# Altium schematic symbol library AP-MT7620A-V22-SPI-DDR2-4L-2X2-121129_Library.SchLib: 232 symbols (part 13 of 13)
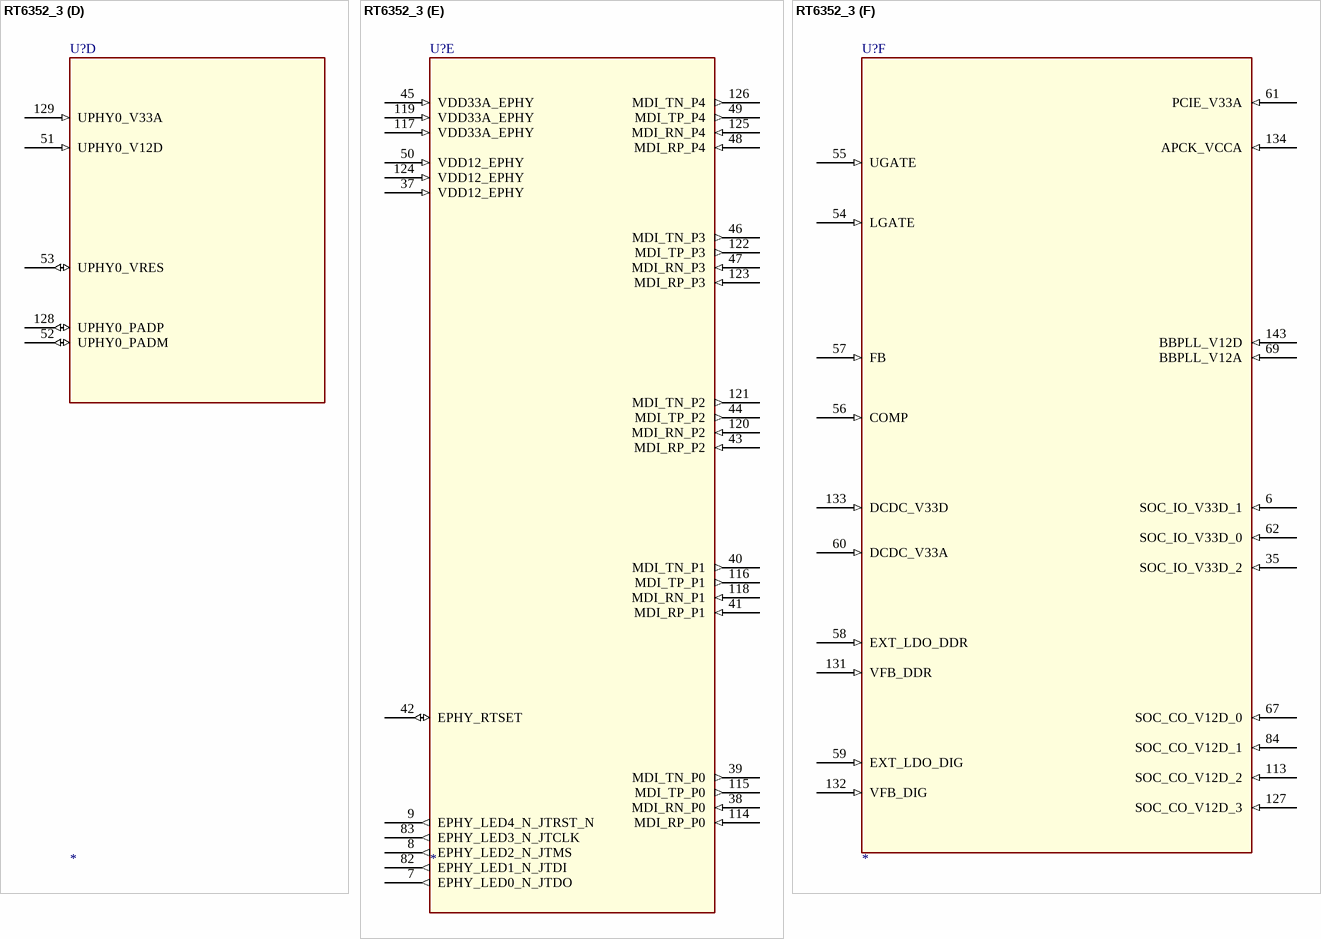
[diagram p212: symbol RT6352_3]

## RT6352_3
designator U?
footprint DRQFN148
part A pins: 1 RF0_PA2_V33N (in), 3 RF1_VX_LDO (out), 4 RF1_OUTP (out), 5 RF1_PA2_V33N (in), 66 PA_PE_G0 (out), 68 ANT_TRN (out), 71 RF_XI (out), 73 PLL_VC_CAP (out), 74 BG_EXTR (out), 75 RF0_OUTN (out), 76 RF0_PA1_V33A (in), 78 RF1_PA2_V33P (in), 79 RF1_OUTN (out), 80 RF1_PA1_V33A (in), 81 WLAN_LED_N (out), 140 PA_PE_G1 (out), 142 ANT_TRNB (out), 144 RF_XO (out), 145 RF_V12_XTAL (out), 146 PLL_VX_LDO (out), 147 BG_V33A (out), 148 RF0_VX_LDO (out), NC RF0_OUTP (out), NC RF0_PA2_V33P (in)
part B pins: 10 VDD18/VDD25 (in), 11 DDR_DQ9/DDR_DQ14 (io), 12 DDR_DQ11/DDR_DQ12 (io), 13 DDR_DQ13/DDR_DQ10 (io), 14 DDR_DQ15/DDR_DQ8 (io), 15 DDR_DQM1/DDR_DQM1 (io), 16 DDR_CLK_M (io), 17 DDR_ODT/DDR_MA4 (io), 18 DDR_IOC_V12D (in), 19 DDR_CAS_N/DDR_MA7 (io), 20 DDR_MA0/DDR_MA8 (io), 21 DDR_MA4/DDR_MA11 (io), 22 DDR_MA8/DDR_CKE (io), 23 DDR_DQ5/DDR_DQ0 (io), 24 DDR_DQ0/DDR_DQ2 (io), 25 DDR_DQ7/DDR_DQ3 (io), 27 DDR_DQ3/DDR_DQ7 (io), 28 DDR_DQM02/DDR_DQM0 (io), 29 DDR_MA12/DDR_MA2 (io), 30 VDD18/VDD25 (in), 31 DDR_MA3/DDR_MA10 (io), 31 DDR_DQM1/DDR_BA0 (io), 33 DDR_BA1/DDR_RAS_N (io), 34 DDR_CKE/DDR_WE_N (io), 85 DDR_DQ14/DDR_DQ15 (io), 86 DDR_DQ12/DDR_DQ13 (io), 87 DDR_DQ10/DDR_DQ11 (io), 88 DDR_DQ8/DDR_DQ9 (io), 89 DDR_DQS1/DDR_DQS1 (in), 90 DDR_VREF (in), 91 DDR_CLK_P (io), 93 DDR_RAS_N/DDR_MA5 (io), 93 VDD18/VDD25 (in), 94 DDR_CS_N/DDR2_MA6 (io), 95 VDD18/VDD25 (in), 96 DDR_MA2/DDR_MA9 (io), 97 DDR_MA6/DDR_MA12 (io), 98 DDR_MA11/DDR_ODT (io), 99 DDR_DQ2/DDR_DQ1 (io), 100 DDR_IOC_V12D (in), 101 DDR_DQ6/DDR_DQ4 (io), 102 DDR_DQ4/DDR_DQ6 (io), 103 DDR_DQS0/DDR_DQS0 (io), 104 DDR_MA9/DDR_MA3 (io), 105 DDR_MA7/DDR_MA1 (io), 106 DDR_MA5/DDR_MA0 (io), 107 DDR_DQ1/DDR_DQ5 (io), 107 DDR_MA1/DDR_BA1 (io), 108 DDR_BA0/DDR_CS_N (io), 109 DDR_WE_N/DDR_CAS_N (io), 110 DDR_VREF (in)
part C pins: 36 I2C_SD (out), 63 SPI_MOSI (out), 64 SPI_CS0 (out), 65 GPIO0 (io), 111 I2C_SCLK (io), 112 RXD2 (in), 130 PORST_N (in), 136 SPI_CLK (out), 137 SPI_MISO (in), 138 SPI_CS1 (out), 139 WDT_RST_N (in), NC TXD2 (out)
part D pins: 51 UPHY0_V12D (in), 52 UPHY0_PADM (io), 53 UPHY0_VRES (io), 128 UPHY0_PADP (io), 129 UPHY0_V33A (in)
part E pins: 7 EPHY_LED0_N_JTDO (out), 8 EPHY_LED2_N_JTMS (out), 9 EPHY_LED4_N_JTRST_N (out), 37 VDD12_EPHY (in), 38 MDI_RN_P0 (in), 39 MDI_TN_P0 (out), 40 MDI_TN_P1 (out), 41 MDI_RP_P1 (in), 42 EPHY_RTSET (io), 43 MDI_RP_P2 (in), 44 MDI_TP_P2 (out), 45 VDD33A_EPHY (in), 46 MDI_TN_P3 (out), 47 MDI_RN_P3 (in), 48 MDI_RP_P4 (in), 49 MDI_TP_P4 (out), 50 VDD12_EPHY (in), 82 EPHY_LED1_N_JTDI (out), 83 EPHY_LED3_N_JTCLK (out), 114 MDI_RP_P0 (in), 115 MDI_TP_P0 (out), 116 MDI_TP_P1 (out), 117 VDD33A_EPHY (in), 118 MDI_RN_P1 (in), 119 VDD33A_EPHY (in), 120 MDI_RN_P2 (in), 121 MDI_TN_P2 (out), 122 MDI_TP_P3 (out), 123 MDI_RP_P3 (in), 124 VDD12_EPHY (in), 125 MDI_RN_P4 (in), 126 MDI_TN_P4 (out)
part F pins: 6 SOC_IO_V33D_1 (in), 35 SOC_IO_V33D_2 (in), 54 LGATE (in), 55 UGATE (in), 56 COMP (in), 57 FB (in), 58 EXT_LDO_DDR (in), 59 EXT_LDO_DIG (in), 60 DCDC_V33A (in), 61 PCIE_V33A (in), 62 SOC_IO_V33D_0 (in), 67 SOC_CO_V12D_0 (in), 69 BBPLL_V12A (in), 84 SOC_CO_V12D_1 (in), 113 SOC_CO_V12D_2 (in), 127 SOC_CO_V12D_3 (in), 131 VFB_DDR (in), 132 VFB_DIG (in), 133 DCDC_V33D (in), 134 APCK_VCCA (in), 143 BBPLL_V12D (in)

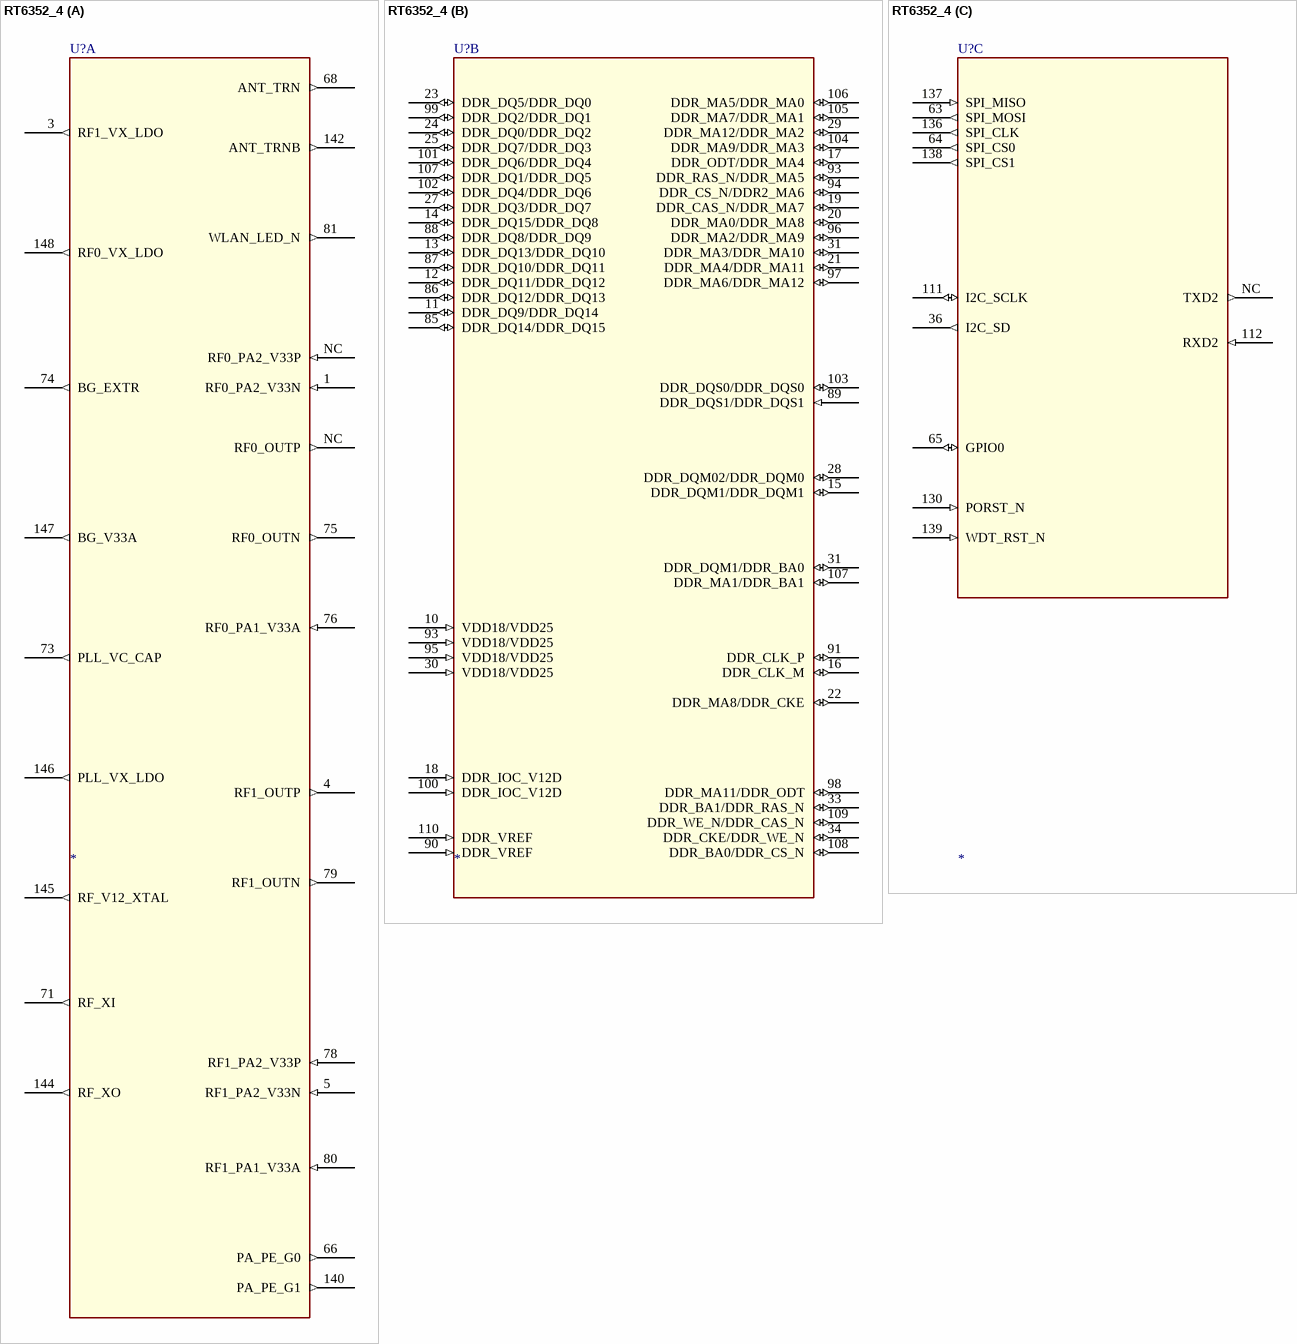
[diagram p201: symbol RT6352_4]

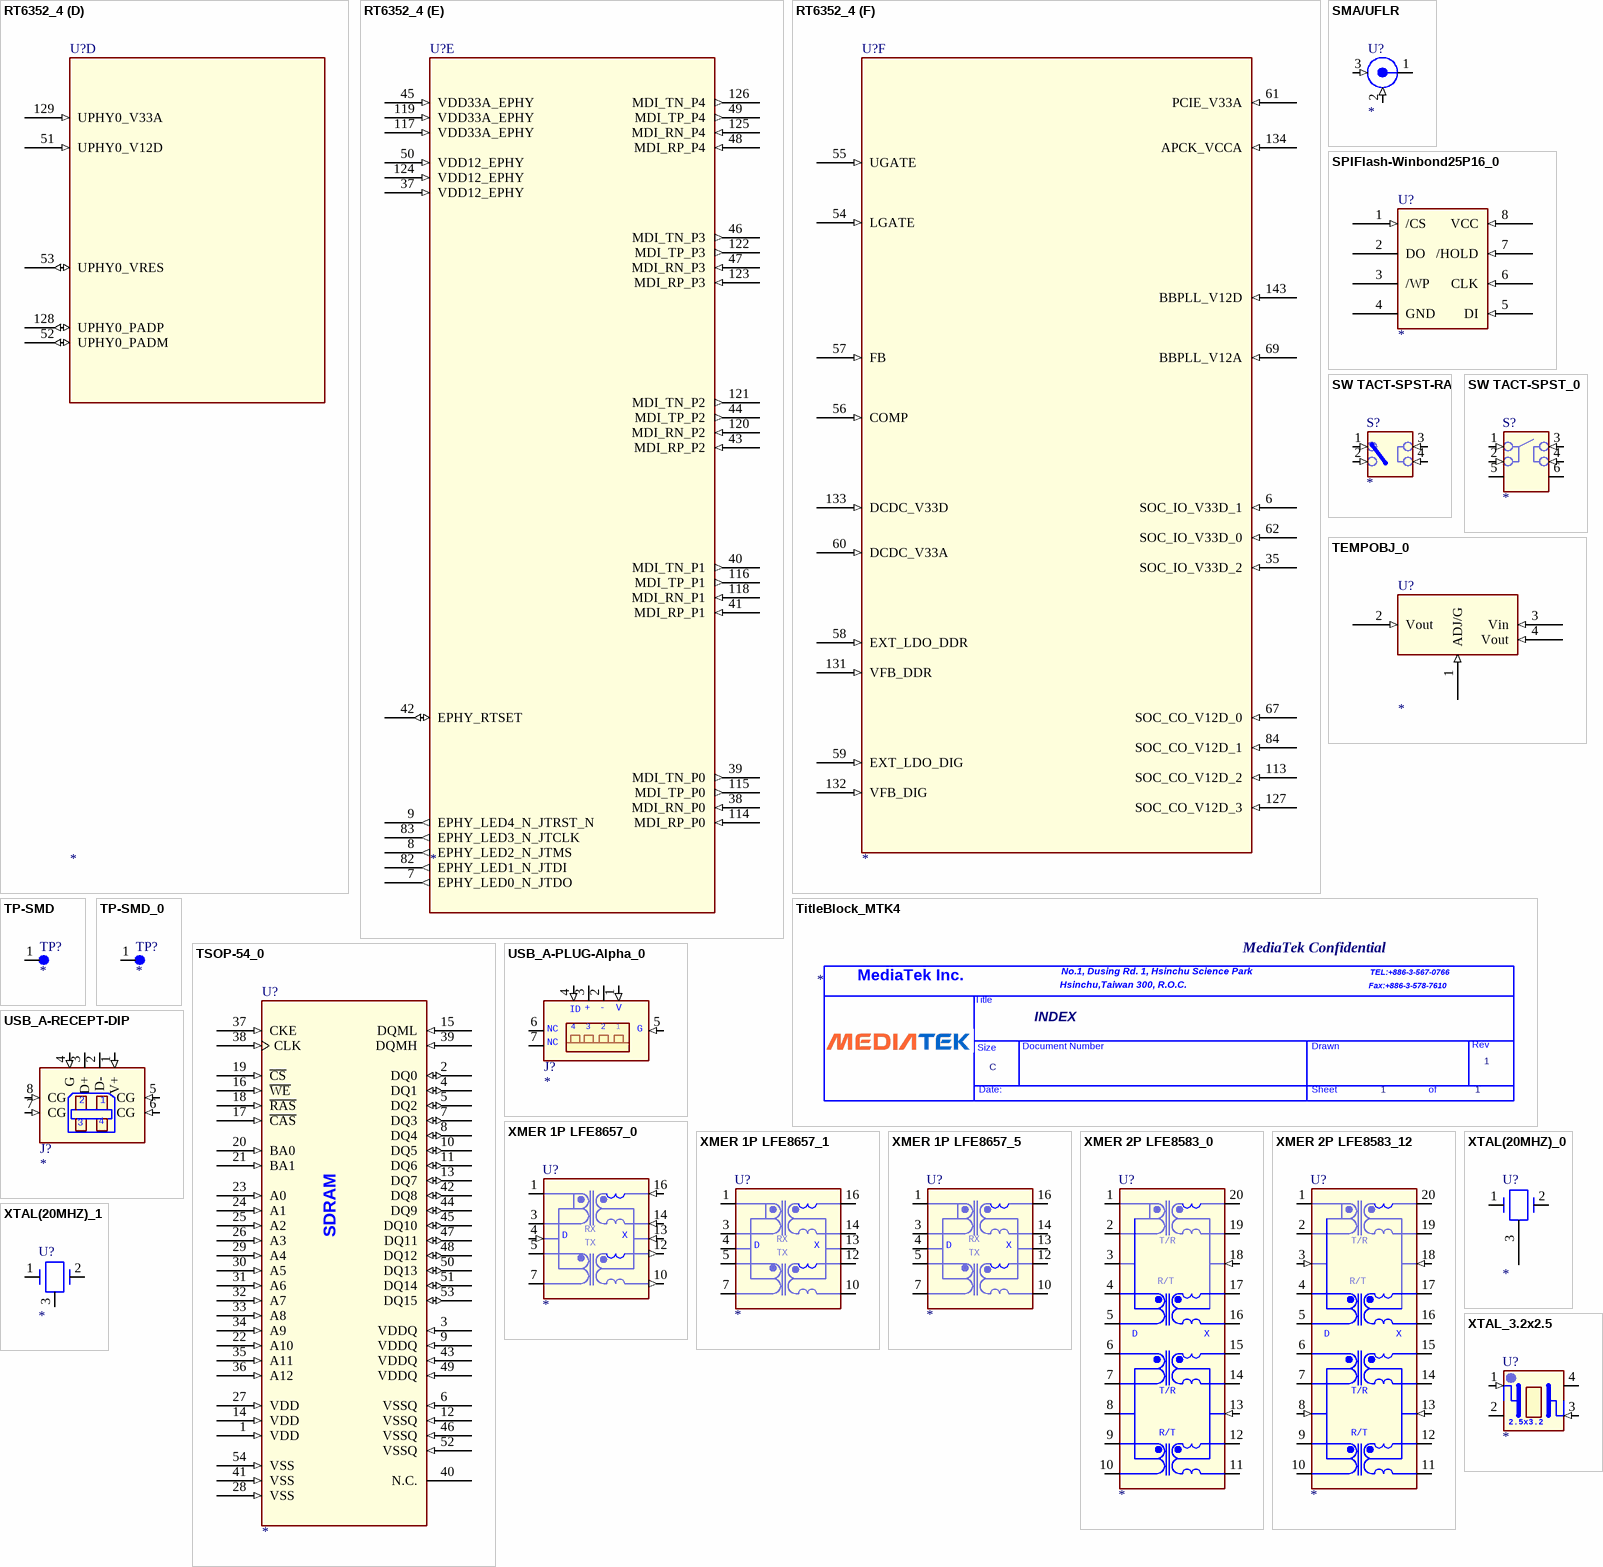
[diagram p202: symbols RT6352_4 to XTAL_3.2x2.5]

## RT6352_4
designator U?
footprint DRQFN148
part A pins: 1 RF0_PA2_V33N (in), 3 RF1_VX_LDO (out), 4 RF1_OUTP (out), 5 RF1_PA2_V33N (in), 66 PA_PE_G0 (out), 68 ANT_TRN (out), 71 RF_XI (out), 73 PLL_VC_CAP (out), 74 BG_EXTR (out), 75 RF0_OUTN (out), 76 RF0_PA1_V33A (in), 78 RF1_PA2_V33P (in), 79 RF1_OUTN (out), 80 RF1_PA1_V33A (in), 81 WLAN_LED_N (out), 140 PA_PE_G1 (out), 142 ANT_TRNB (out), 144 RF_XO (out), 145 RF_V12_XTAL (out), 146 PLL_VX_LDO (out), 147 BG_V33A (out), 148 RF0_VX_LDO (out), NC RF0_OUTP (out), NC RF0_PA2_V33P (in)
part B pins: 10 VDD18/VDD25 (in), 11 DDR_DQ9/DDR_DQ14 (io), 12 DDR_DQ11/DDR_DQ12 (io), 13 DDR_DQ13/DDR_DQ10 (io), 14 DDR_DQ15/DDR_DQ8 (io), 15 DDR_DQM1/DDR_DQM1 (io), 16 DDR_CLK_M (io), 17 DDR_ODT/DDR_MA4 (io), 18 DDR_IOC_V12D (in), 19 DDR_CAS_N/DDR_MA7 (io), 20 DDR_MA0/DDR_MA8 (io), 21 DDR_MA4/DDR_MA11 (io), 22 DDR_MA8/DDR_CKE (io), 23 DDR_DQ5/DDR_DQ0 (io), 24 DDR_DQ0/DDR_DQ2 (io), 25 DDR_DQ7/DDR_DQ3 (io), 27 DDR_DQ3/DDR_DQ7 (io), 28 DDR_DQM02/DDR_DQM0 (io), 29 DDR_MA12/DDR_MA2 (io), 30 VDD18/VDD25 (in), 31 DDR_MA3/DDR_MA10 (io), 31 DDR_DQM1/DDR_BA0 (io), 33 DDR_BA1/DDR_RAS_N (io), 34 DDR_CKE/DDR_WE_N (io), 85 DDR_DQ14/DDR_DQ15 (io), 86 DDR_DQ12/DDR_DQ13 (io), 87 DDR_DQ10/DDR_DQ11 (io), 88 DDR_DQ8/DDR_DQ9 (io), 89 DDR_DQS1/DDR_DQS1 (in), 90 DDR_VREF (in), 91 DDR_CLK_P (io), 93 DDR_RAS_N/DDR_MA5 (io), 93 VDD18/VDD25 (in), 94 DDR_CS_N/DDR2_MA6 (io), 95 VDD18/VDD25 (in), 96 DDR_MA2/DDR_MA9 (io), 97 DDR_MA6/DDR_MA12 (io), 98 DDR_MA11/DDR_ODT (io), 99 DDR_DQ2/DDR_DQ1 (io), 100 DDR_IOC_V12D (in), 101 DDR_DQ6/DDR_DQ4 (io), 102 DDR_DQ4/DDR_DQ6 (io), 103 DDR_DQS0/DDR_DQS0 (io), 104 DDR_MA9/DDR_MA3 (io), 105 DDR_MA7/DDR_MA1 (io), 106 DDR_MA5/DDR_MA0 (io), 107 DDR_DQ1/DDR_DQ5 (io), 107 DDR_MA1/DDR_BA1 (io), 108 DDR_BA0/DDR_CS_N (io), 109 DDR_WE_N/DDR_CAS_N (io), 110 DDR_VREF (in)
part C pins: 36 I2C_SD (out), 63 SPI_MOSI (out), 64 SPI_CS0 (out), 65 GPIO0 (io), 111 I2C_SCLK (io), 112 RXD2 (in), 130 PORST_N (in), 136 SPI_CLK (out), 137 SPI_MISO (in), 138 SPI_CS1 (out), 139 WDT_RST_N (in), NC TXD2 (out)
part D pins: 51 UPHY0_V12D (in), 52 UPHY0_PADM (io), 53 UPHY0_VRES (io), 128 UPHY0_PADP (io), 129 UPHY0_V33A (in)
part E pins: 7 EPHY_LED0_N_JTDO (out), 8 EPHY_LED2_N_JTMS (out), 9 EPHY_LED4_N_JTRST_N (out), 37 VDD12_EPHY (in), 38 MDI_RN_P0 (in), 39 MDI_TN_P0 (out), 40 MDI_TN_P1 (out), 41 MDI_RP_P1 (in), 42 EPHY_RTSET (io), 43 MDI_RP_P2 (in), 44 MDI_TP_P2 (out), 45 VDD33A_EPHY (in), 46 MDI_TN_P3 (out), 47 MDI_RN_P3 (in), 48 MDI_RP_P4 (in), 49 MDI_TP_P4 (out), 50 VDD12_EPHY (in), 82 EPHY_LED1_N_JTDI (out), 83 EPHY_LED3_N_JTCLK (out), 114 MDI_RP_P0 (in), 115 MDI_TP_P0 (out), 116 MDI_TP_P1 (out), 117 VDD33A_EPHY (in), 118 MDI_RN_P1 (in), 119 VDD33A_EPHY (in), 120 MDI_RN_P2 (in), 121 MDI_TN_P2 (out), 122 MDI_TP_P3 (out), 123 MDI_RP_P3 (in), 124 VDD12_EPHY (in), 125 MDI_RN_P4 (in), 126 MDI_TN_P4 (out)
part F pins: 6 SOC_IO_V33D_1 (in), 35 SOC_IO_V33D_2 (in), 54 LGATE (in), 55 UGATE (in), 56 COMP (in), 57 FB (in), 58 EXT_LDO_DDR (in), 59 EXT_LDO_DIG (in), 60 DCDC_V33A (in), 61 PCIE_V33A (in), 62 SOC_IO_V33D_0 (in), 67 SOC_CO_V12D_0 (in), 69 BBPLL_V12A (in), 84 SOC_CO_V12D_1 (in), 113 SOC_CO_V12D_2 (in), 127 SOC_CO_V12D_3 (in), 131 VFB_DDR (in), 132 VFB_DIG (in), 133 DCDC_V33D (in), 134 APCK_VCCA (in), 143 BBPLL_V12D (in)

## SMA/UFLR
designator U?
footprint UFLR
pins: 1, 2 (in), 3 GNDA (in)

## SPIFlash-Winbond25P16_0
designator U?
pins: 1 /CS (in), 2 DO, 3 /WP, 4 GND, 5 DI (in), 6 CLK (in), 7 /HOLD (in), 8 VCC (in)

## SW TACT-SPST-RA
designator S?
footprint SW2P
pins: 1 (in), 2 (in), 3 (in), 4 (in)

## SW TACT-SPST_0
designator S?
footprint SW6P
pins: 1 (in), 2 (in), 3 (in), 4 (in), 5 -, 6 +

## TEMPOBJ_0
designator U?
footprint SOT-223
pins: 1 ADJ/G (in), 2 Vout (in), 3 Vin (in), 4 Vout (in)

## TitleBlock_MTK4
designator *  PIM: MediaTek Confidential  Page Count: 1  Page Size: C  Title: INDEX  (graphical)

## TP-SMD
designator TP?
footprint TP-SMD
pins: 1

## TP-SMD_0
designator TP?
footprint TP-SMD
pins: 1 (io)

## TSOP-54_0
designator U?
pins: 1 VDD (in), 2 DQ0 (io), 3 VDDQ (in), 4 DQ1 (io), 5 DQ2 (io), 6 VSSQ (in), 7 DQ3 (io), 8 DQ4 (io), 9 VDDQ (in), 10 DQ5 (io), 11 DQ6 (io), 12 VSSQ (in), 13 DQ7 (io), 14 VDD (in), 15 DQML (in), 16 ~{WE} (in), 17 ~{CAS} (in), 18 ~{RAS} (in), 19 ~{CS} (in), 20 BA0 (in), 21 BA1 (in), 22 A10 (in), 23 A0 (in), 24 A1 (in), 25 A2 (in), 26 A3 (in), 27 VDD (in), 28 VSS (in), 29 A4 (in), 30 A5 (in), 31 A6 (in), 32 A7 (in), 33 A8 (in), 34 A9 (in), 35 A11 (in), 36 A12 (in), 37 CKE (in), 38 CLK (in), 39 DQMH (in), 40 N.C., 41 VSS (in), 42 DQ8 (io), 43 VDDQ (in), 44 DQ9 (io), 45 DQ10 (io), 46 VSSQ (in), 47 DQ11 (io), 48 DQ12 (io), 49 VDDQ (in), 50 DQ13 (io), 51 DQ14 (io), 52 VSSQ (in), 53 DQ15 (io), 54 VSS (in)

## USB_A-PLUG-Alpha_0
designator J?
Schematics' Source Library: C:\MSim_8\UserLib\vnet2.slb
footprint USB-A-PLUG-Alpha
pins: 1 V+ (in), 2 D- (hiz), 3 D+ (hiz), 4 G (in), 5 G (in), 6 NC, 7 NC

## USB_A-RECEPT-DIP
designator J?
Schematics' Source Library: C:\MSim_8\UserLib\vnet2.slb
footprint USB_A-RECEPT-R/A-DIP
pins: 1 V+ (in), 2 D- (hiz), 3 D+ (hiz), 4 G (in), 5 CG (in), 6 CG (in), 7 CG (in), 8 CG (in)

## XMER 1P LFE8657_0
designator U?
footprint DIP-16PIN-2010
pins: 1 RD+ (io), 3 RD- (io), 4 CT (in), 5 TD+ (io), 7 TD- (io), 10 TX- (out), 12 TX+ (out), 13 CG (in), 14 RX- (in), 16 RX+ (in)

## XMER 1P LFE8657_1
designator U?
footprint DIP-16PIN-2010
pins: 1 RD+, 3 RD-, 4 CT, 5 TD+, 7 TD-, 10 TX- (io), 12 TX+ (io), 13 CG (io), 14 RX- (io), 16 RX+ (io)

## XMER 1P LFE8657_5
designator U?
footprint DIP-16PIN-2010
pins: 1 RD+ (io), 3 RD- (io), 4 CT (io), 5 TD+ (io), 7 TD- (io), 10 TX- (io), 12 TX+ (io), 13 CG (io), 14 RX- (io), 16 RX+ (io)

## XMER 2P LFE8583_0
designator U?
footprint DIP-20PIN-2510
pins: 1 TRD+1, 2 TRD-1, 3 CT1, 4 RTD+1, 5 RTD-1, 6 TRD+2, 7 TRD+2, 8 CT2, 9 RTD+2, 10 RTD-2, 11 RTX-2 (io), 12 RTX+2 (io), 13 CTX2 (in), 14 TRX-1 (io), 15 TRX+2 (io), 16 RTX-1 (io), 17 RTX+1 (io), 18 CTX1 (in), 19 TRX-1 (io), 20 TRX+1 (io)

## XMER 2P LFE8583_12
designator U?
footprint DIP-20PIN-2510
pins: 1 TRD+1 (io), 2 TRD-1 (io), 3 CT1 (in), 4 RTD+1 (io), 5 RTD-1 (io), 6 TRD+2 (io), 7 TRD+2 (io), 8 CT2 (in), 9 RTD+2 (io), 10 RTD-2 (io), 11 RTX-2 (io), 12 RTX+2 (io), 13 CTX2 (in), 14 TRX-1 (io), 15 TRX+2 (io), 16 RTX-1 (io), 17 RTX+1 (io), 18 CTX1 (in), 19 TRX-1 (io), 20 TRX+1 (io)

## XTAL(20MHZ)_0
designator U?
Parnt_desc: XTAL 20MHz 30ppm HC-49/U; Parent: 24-020060-40
footprint DIP
pins: 1, 2, 3

## XTAL(20MHZ)_1
designator U?
Parnt_desc: XTAL 20MHz 30ppm HC-49/U; Parent: 24-020060-40
footprint DIP
pins: 1, 2, 3

## XTAL_3.2x2.5
designator U?
footprint XTAL-SMD/3.2X2.5
pins: 1 X1 (in), 2 NC, 3 X2 (in), 4 NC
